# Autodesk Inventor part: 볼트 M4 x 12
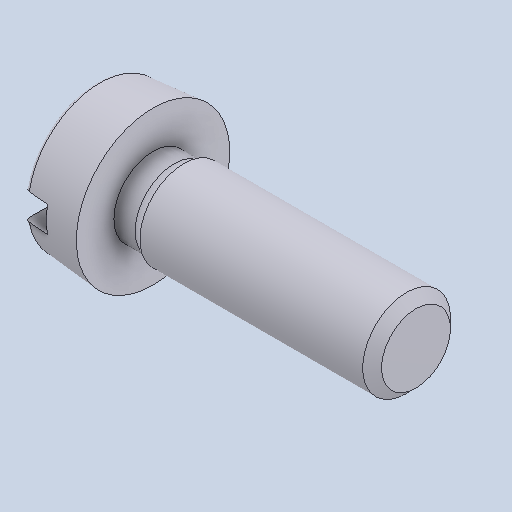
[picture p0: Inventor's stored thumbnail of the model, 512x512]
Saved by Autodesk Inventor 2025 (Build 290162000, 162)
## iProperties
Created: 2025-08
Part Number: 볼트 M4 x 12
Material: 강철, 연강
Description: 6각머리 태핑 나사
Document SubType Name: Modeling
Designer: infra017
Density: 7.85 g/cm^3
Appearance: 기본값
Author: jhkim
Sending System: Autodesk Inventor 2026
Preprocessor: ST-DEVELOPER v20.1
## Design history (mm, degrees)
feature "Solid1"
node "솔리드1"
